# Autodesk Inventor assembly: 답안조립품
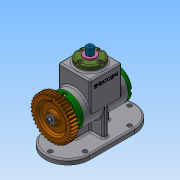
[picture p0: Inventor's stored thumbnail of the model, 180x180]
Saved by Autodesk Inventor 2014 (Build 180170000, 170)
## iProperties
Created: 2020-01
Part Number: 답안조립품
Document SubType Name: Assembly
Designer: net
Mass: 1339.33 g
Surface Area: 1737.15 cm^2
Volume: 590.166 cm^3
Density: 2.26941 g/cm^3
Author: net
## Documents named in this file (18)
- C:\Users\net\Desktop\600104V1036\답안조립품.iam
- C:\Users\net\Desktop\600104V1036\본체.ipt
- C:\Users\net\Desktop\600104V1036\뒤커버.ipt
- C:\Users\net\Desktop\600104V1036\베어링 6203.ipt
- C:\Users\net\Desktop\600104V1036\볼트 M4.ipt
- C:\Users\net\Desktop\600104V1036\부시.ipt
- C:\Users\net\Desktop\600104V1036\슬라이더.ipt
- C:\Users\net\Desktop\600104V1036\스프링조립용 와셔.ipt
- C:\Users\net\Desktop\600104V1036\상부커버.ipt
- C:\Users\net\Desktop\600104V1036\편심축.ipt
- C:\Users\net\Desktop\600104V1036\키 4x4x12.ipt
- C:\Users\net\Desktop\600104V1036\앞커버.ipt
- C:\Users\net\Desktop\600104V1036\오일 실 17 30 5.ipt
- C:\Users\net\Desktop\600104V1036\스퍼기어.ipt
- C:\Users\net\Desktop\600104V1036\평와셔.ipt
- C:\Users\net\Desktop\600104V1036\스프링와셔.ipt
- C:\Users\net\Desktop\600104V1036\멈춤링.ipt
- C:\Users\net\Desktop\600104V1036\가변스프링.ipt
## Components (1 placed, 1 different names)
1. 가변스프링:1
